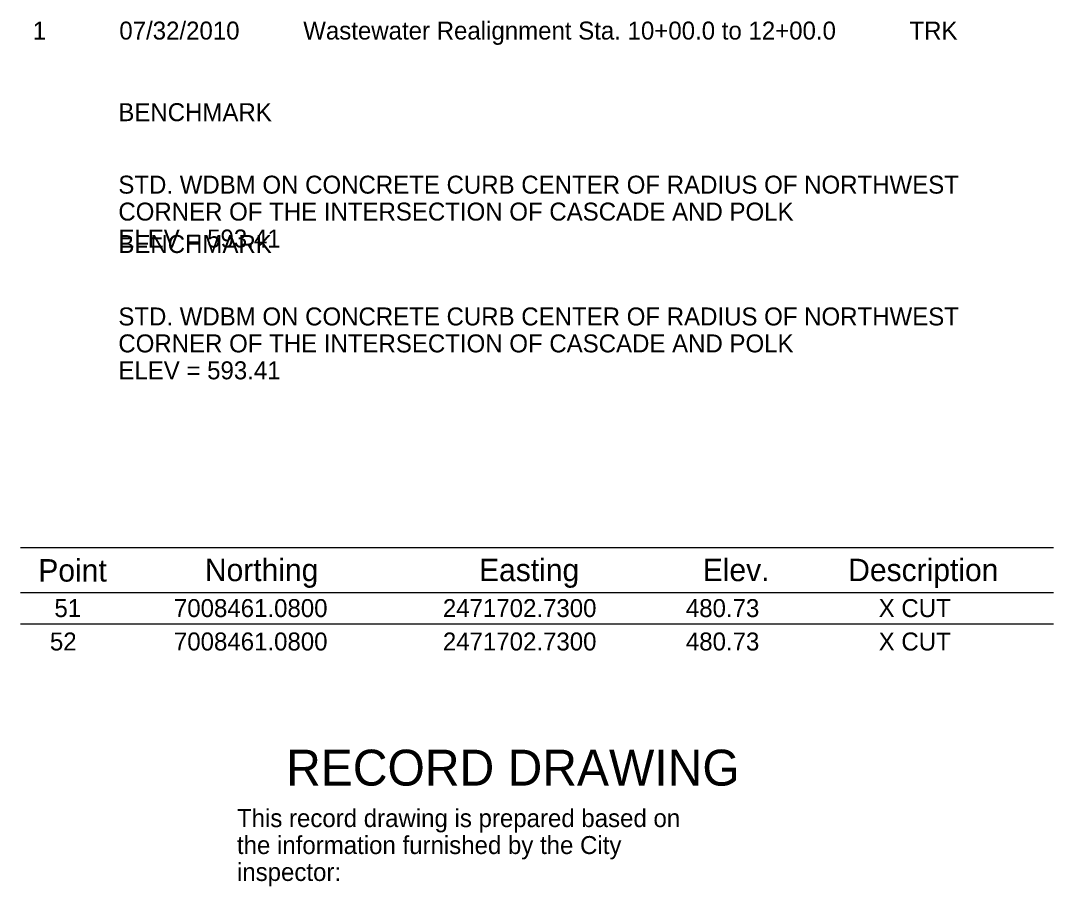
# Model space of a CAD drawing. Extents: x -2311 to -1444, y -1548 to -1045.
# Drawn here: x -1575.7 to -1460.7, y -1417 to -1320.6 of the extents above; entities that cross this region are included whole.
import ezdxf

# ---------------------------------------------------------------- set-up
doc = ezdxf.new("R2010")
doc.units = 0
doc.layers.add('G_BORDER', color=7, linetype='Continuous')
doc.layers.add('G_SIGNATURE BLOCK', color=7, linetype='Continuous')

msp = doc.modelspace()

# ---------------------------------------------------------------- linework, layer by layer
at = {"layer": 'G_BORDER'}
for p, q in [((-1575.75, -1379.26), (-1460.75, -1379.26)), ((-1575.75, -1384.26), (-1460.75, -1384.26)), ((-1575.75, -1387.76), (-1460.75, -1387.76))]:
    msp.add_line(p, q, dxfattribs=at)

# ---------------------------------------------------------------- texts
for s, height, p in [('1', 2, (-1574.4, -1322.69)), ('07/32/2010', 2, (-1564.76, -1322.69)), ('Wastewater Realignment Sta. 10+00.0 to 12+00.0', 2, (-1544.28, -1322.69)), ('TRK', 2, (-1476.77, -1322.69)), ('BENCHMARK', 2, (-1564.87, -1331.78)), ('STD. WDBM ON CONCRETE CURB CENTER OF RADIUS OF NORTHWEST', 2, (-1564.87, -1339.85)), ('CORNER OF THE INTERSECTION OF CASCADE AND POLK', 2, (-1564.87, -1342.85)), ('ELEV = 593.41', 2, (-1564.87, -1345.85)), ('BENCHMARK', 2, (-1564.87, -1346.46)), ('STD. WDBM ON CONCRETE CURB CENTER OF RADIUS OF NORTHWEST', 2, (-1564.87, -1354.53)), ('CORNER OF THE INTERSECTION OF CASCADE AND POLK', 2, (-1564.87, -1357.53)), ('ELEV = 593.41', 2, (-1564.87, -1360.53)), ('Point', 2.5, (-1573.78, -1383.06)), ('Northing', 2.5, (-1555.23, -1383.01)), ('Easting', 2.5, (-1524.7, -1383.01)), ('Elev.', 2.5, (-1499.79, -1383.01)), ('Description', 2.5, (-1483.59, -1383.01)), ('51', 2, (-1571.99, -1387.01)), ('7008461.0800', 2, (-1558.68, -1387.01)), ('2471702.7300', 2, (-1528.73, -1387.01)), ('480.73', 2, (-1501.67, -1387.01)), ('X CUT', 2, (-1480.2, -1387.01)), ('52', 2, (-1572.49, -1390.73)), ('7008461.0800', 2, (-1558.68, -1390.73)), ('2471702.7300', 2, (-1528.73, -1390.73)), ('480.73', 2, (-1501.67, -1390.73)), ('X CUT', 2, (-1480.2, -1390.73))]:
    msp.add_text(s, height=height, dxfattribs=at).set_placement(p)
at = {"layer": 'G_SIGNATURE BLOCK'}
msp.add_text('RECORD DRAWING', height=4, rotation=360, dxfattribs=at).set_placement((-1546.19, -1405.78))
for s, p in [('This record drawing is prepared based on', (-1551.66, -1410.4)), ('the information furnished by the City', (-1551.66, -1413.4)), ('inspector:', (-1551.66, -1416.4))]:
    msp.add_text(s, height=2, dxfattribs=at).set_placement(p)

doc.saveas('drawing.dxf')
